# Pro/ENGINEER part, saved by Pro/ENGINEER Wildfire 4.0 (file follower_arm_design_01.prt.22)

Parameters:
  METRIC = "NO"

Other parameters: PITCH, DRILL_DIAMETER, THREAD_DIAMETER, THREADS_PER_INCH, THREAD_DEPTH, THREAD_LENGTH, DRILL_POINT_ANGLE, DRILL_DEPTH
